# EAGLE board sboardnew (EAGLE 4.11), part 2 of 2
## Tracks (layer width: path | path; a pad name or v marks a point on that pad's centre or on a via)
-15V  (via drill 0.61)
  Top 0.635: v61.59,20.32 v56.52,15.24 | v203.2,28.58 v189.87,15.24
  Bottom 0.635: v56.52,15.24 55.88,15.24 55.88,13.97 U$1.DB2 | 117.47,20.32 v61.59,20.32 | 117.47,20.32 123.83,13.97 U$1.CB2 | 117.47,20.32 136.53,20.32 139.7,17.15 184.15,17.15 187.32,13.97 U$1.BB2 188.59,13.97 v189.87,15.24 | v203.2,28.58 232.41,28.58 242.57,18.42 252.73,18.42 257.18,13.97 U$1.AB2
A15U1  (via drill 0.61)
  Top 0.254: R11.2 R12.1 205.74,47.63 206.38,46.99 206.38,39.37 207.65,38.1 v207.65,15.88
  Bottom 0.254: v207.65,15.88 209.55,13.97 U$1.AU2
B17S1  (via drill 0.61)
  Top 0.254: E39.4 28.57,83.19 28.57,87 E39.1 | v216.53,179.07 217.81,177.8 217.81,121.29 E6.4 | v178.44,80.01 178.44,114.94 E12.4
  Bottom 0.254: 40.01,80.01 40.01,78.11 E39.9 | 40.01,80.01 33.02,80.01 31.75,81.28 E39.4 | E6.10 219.71,114.3 217.17,116.84 E6.4 209.55,116.84 207.01,114.3 E9.10 203.2,114.3 201.93,115.57 182.88,115.57 181.61,116.84 E12.4 | v216.53,179.07 215.9,179.07 214.63,180.34 E8.3 | v178.44,80.01 40.01,80.01
B17V1  (via drill 0.61)
  Top 0.254: E9.13 210.82,121.92 210.82,123.19 212.09,124.46 E6.1 | E3.3 230.5,118.75 230.5,117.48 E3.4 229.24,114.94 229.24,93.98 230.5,92.71 230.5,89.54 E2.1 | 226.06,82.55 R16.1 | 226.06,82.55 R15.2 | 226.06,82.55 222.25,86.36 E5.13 | E42.1 17.78,55.88 17.78,86.36 E43.1 | v147.96,86.36 147.96,53.98 E17.1
  Bottom 0.254: 223.52,120.65 224.79,119.38 E3.3 | 223.52,120.65 222.25,121.92 E6.13 | 223.52,120.65 208.28,120.65 207.01,121.92 E9.13 | E5.13 217.17,86.36 214.63,88.9 E5.1 212.09,88.9 209.55,86.36 v147.96,86.36 | R15.2 226.06,84.46 226.69,84.46 E2.1 234.95,88.9 237.49,86.36 E2.13 | E17.13 153.67,50.8 151.13,53.34 E17.1 146.05,53.34 143.51,50.8 E18.13 135.89,50.8 133.35,53.34 E18.1 130.81,53.34 129.54,54.61 34.29,54.61 31.75,52.07 17.78,52.07 | 17.78,52.07 19.05,50.8 E42.13 | 17.78,52.07 16.51,53.34 E42.1 | E43.13 21.59,86.36 19.05,88.9 E43.1
D01BINIT  (via drill 0.61)
  Top 0.254: v169.54,51.44 169.54,112.4 E15.4
  Bottom 0.254: E4.2 197.49,58.42 188.59,49.53 175.26,49.53 173.99,48.26 E14.15 v169.54,51.44
D01BTP2L  (via drill 0.61)
  Top 0.254: v177.16,123.83 177.8,124.46 177.8,144.78 E13.4
  Bottom 0.254: 177.16,123.19 228.6,123.19 229.87,121.92 E3.2 E3.13 | 177.16,123.19 167.64,123.19 166.37,121.92 E15.2 | 177.16,123.19 v177.16,123.83
D01DEL1H  (via drill 0.61)
  Top 0.254: v158.75,125.1 159.38,125.73 v159.38,128.27 159.38,144.15 E16.3
  Bottom 0.254: v158.75,125.1 149.22,115.57 121.92,115.57 118.11,111.76 E24.9 | v159.38,128.27 240.66,128.27 240.66,121.29 240.03,120.65 237.49,120.65 E3.5
D01DEL1L
  Top 0.254: E9.4 196.22,118.75 196.22,145.42 E10.4
  Bottom 0.254: E3.6 229.87,111.76 226.06,115.57 219.71,115.57 217.17,118.11 209.55,118.11 207.01,115.57 203.2,115.57 201.93,116.84 E9.4
D01DEL2  (via drill 0.61)
  Top 0.254: 116.2,57.79 104.78,57.79 100.33,53.34 E28.1 | 116.2,57.79 116.2,48.9 E22.1 | 116.2,57.79 116.84,58.42 116.84,72.39 118.11,72.39 118.75,73.03 118.75,89.54 114.94,93.35 114.94,114.94 E24.7 118.75,118.75 118.75,148.59 115.57,151.77 115.57,154.31 v120.02,158.75
  Bottom 0.254: v120.02,158.75 160.02,158.75 163.83,154.94 E16.1
D01DEL3  (via drill 0.61)
  Top 0.254: v192.41,127 195.58,130.18 195.58,147.32 E10.3
  Bottom 0.254: v192.41,127 E24.18 | E10.11 204.47,147.32 203.2,148.59 200.66,148.59 199.39,149.86 E10.3
D01DEL4
  Top 0.254: E3.9 236.85,113.67 236.85,139.07 238.12,140.34 238.12,181.61 231.78,187.96 196.22,187.96 196.22,182.25 E11.3 | E13.11 186.06,149.23 186.06,161.93 195.58,171.45 195.58,177.8 E11.3 | E9.3 201.29,122.56 201.29,177.17 E11.3
  Bottom 0.254: 121.92,123.19 101.6,123.19 100.33,124.46 E29.1 | 121.92,123.19 123.19,121.92 E24.16 | 121.92,123.19 121.92,128.27 142.24,128.27 142.88,127.64 155.57,127.64 165.1,137.16 165.1,138.43 181.61,138.43 186.69,143.51 189.23,143.51 189.87,144.15 189.87,146.69 188.59,146.69 E13.11
D01DEL5  (via drill 0.61)
  Top 0.254: v174.62,125.73 177.16,128.27 177.16,146.69 178.44,147.96 | 178.44,147.96 E13.3 | v194.31,171.45 178.44,155.58 178.44,147.96
  Bottom 0.254: v174.62,125.73 173.99,126.37 135.25,126.37 125.73,116.84 E24.14 | v194.31,171.45 203.2,171.45 204.47,172.72 E11.9
D01DONEH  (via drill 0.61)
  Top 0.254: v15.88,30.48 15.88,15.24 14.61,13.97 U$1.DS1 | v172.72,65.41 E15.8
  Bottom 0.254: v172.72,65.41 23.5,65.41 12.7,54.61 12.7,30.48 v15.88,30.48
D01DONEL  (via drill 0.61)
  Top 0.254: v167.64,111.76 166.37,113.03 163.19,113.03 163.19,132.08 167.64,136.53 v167.64,166.37
  Bottom 0.254: v167.64,166.37 170.18,168.91 | 170.18,168.91 201.93,168.91 203.2,170.18 E11.8 | v167.64,111.76 E15.9 | 170.18,168.91 169.54,168.91 151.13,187.33 139.06,187.33 E21.7
D01INHIBIT  (via drill 0.61)
  Top 0.254: v224.16,39.37 223.52,38.74 v223.52,15.24
  Bottom 0.254: v224.16,39.37 219.71,39.37 219.07,40.01 215.26,40.01 214.63,40.64 E4.9 | v223.52,15.24 223.52,13.97 U$1.AP2
D01INITL  (via drill 0.61)
  Top 0.254: 189.87,140.97 189.87,150.5 E13.13 189.23,152.4 v191.77,154.94 | 189.87,140.97 189.87,123.83 E12.13 | v197.49,57.15 177.16,77.47 177.16,121.29 E12.1 180.97,125.1 180.97,129.54 182.88,131.45 182.88,140.97 189.87,140.97 | v197.49,127 197.49,125.1 E9.1
  Bottom 0.254: E10.13 206.38,153.04 207.65,153.04 207.65,155.58 207.01,156.21 200.66,156.21 199.39,154.94 E10.1 v191.77,154.94 | E13.1 181.61,154.94 184.15,152.4 E13.13 | v197.49,57.15 218.44,57.15 219.71,55.88 E4.18 | v197.49,127 194.31,127 193.04,125.73 182.88,125.73 181.61,124.46 E12.1
D01LOADMDL  (via drill 0.61)
  Top 0.254: E39.5 32.38,80.65 32.38,84.46 E39.2 33.02,88.9 33.02,147.96 v33.66,148.59
  Bottom 0.254: E39.5 E39.10 | v33.66,148.59 48.26,148.59 58.42,158.75 90.81,158.75 90.81,181.61 95.89,186.69 99.69,186.69 102.23,189.23 151.76,189.23 168.28,172.72 E11.6
D01MEMDONEL
  Bottom 0.254: E21.5 143.51,186.69 150.5,186.69 151.13,186.06 151.13,181.61 126.36,181.61 125.09,180.34 H05/H24.28
D01MEMSTARTL  (via drill 0.61)
  Top 0.254: v223.52,114.3 223.52,116.84 E3.1
  Bottom 0.254: 185.42,113.03 186.69,114.3 E12.10 | 185.42,113.03 182.88,110.49 167.64,110.49 166.37,111.76 E15.6 | v223.52,114.3 222.25,113.03 185.42,113.03
D01POWEROK  (via drill 0.61)
  Top 0.254: v158.75,115.57 v158.75,31.12 | v142.88,18.42 v139.7,15.24
  Bottom 0.254: v158.75,115.57 160.02,115.57 163.83,119.38 E15.3 | v158.75,31.12 153.03,25.4 149.86,25.4 v142.88,18.42 | v139.7,15.24 138.43,13.97 U$1.BV2
D01READH  (via drill 0.61)
  Top 0.254: E11.4 197.49,177.17 197.49,175.9 E11.5 196.22,173.36 196.22,149.23 190.5,143.51 190.5,114.3 E12.9 | E3.11 238.12,116.21 238.12,114.94 E3.10 | v194.31,173.99 E16.13
  Bottom 0.254: E16.13 E16.2 | E12.9 189.23,111.76 190.5,110.49 233.68,110.49 237.49,114.3 E3.10 | v194.31,173.99 195.58,175.26 E11.5
D01READL  (via drill 0.61)
  Top 0.254: 190.5,109.22 196.22,109.22 196.22,114.94 196.85,115.57 201.93,115.57 201.93,151.13 204.47,153.67 207.65,153.67 207.65,173.36 E11.10 205.1,175.9 205.1,177.17 E11.11 | 190.5,109.22 E12.8 | v240.03,16.51 v238.76,15.24 | v205.74,27.31 198.75,34.29 198.75,95.89 190.5,104.14 190.5,109.22
  Bottom 0.254: v238.76,15.24 238.12,15.24 236.85,13.97 U$1.AK2 | v240.03,16.51 233.68,22.86 213.36,22.86 208.91,27.31 v205.74,27.31
D01RETURN  (via drill 0.61)
  Top 0.254: v222.25,15.24 222.88,15.88 222.88,48.9 E4.16
  Bottom 0.254: v222.25,15.24 220.98,13.97 U$1.AR2
D01SELECTH  (via drill 0.61)
  Top 0.254: v161.93,44.45 160.66,45.72 v160.66,117.48 | v182.25,120.65 182.25,116.21 E12.5
  Bottom 0.254: v161.93,44.45 170.18,44.45 171.45,43.18 E14.13 | v160.66,117.48 163.83,120.65 v182.25,120.65
D01SELECTL  (via drill 0.61)
  Top 0.254: v152.4,113.03 149.86,115.57 149.86,152.4 140.97,161.29 140.97,172.72 137.16,176.53 E21.2 137.16,181.61 139.7,184.15 E21.6
  Bottom 0.254: v152.4,113.03 177.8,113.03 179.07,111.76 E12.6
D01SELH  (via drill 0.61)
  Top 0.254: v184.15,130.18 184.15,125.73 E12.2
  Bottom 0.254: v184.15,130.18 194.94,140.97 210.82,140.97 212.09,142.24 E7.6
D01SELL
  Top 0.254: E7.5 210.82,147.32 210.82,185.42 212.09,186.69 219.07,186.69 219.07,179.71 E8.11
D01SOURCE  (via drill 0.61)
  Top 0.254: v222.88,54.61 227.33,50.17 v227.33,33.66 | v229.87,31.12 230.5,30.48 v230.5,15.24
  Bottom 0.254: v222.88,54.61 215.9,54.61 214.63,55.88 E4.3 | v229.87,31.12 v227.33,33.66 | v230.5,15.24 231.78,13.97 U$1.AL2
D01STROBE  (via drill 0.61)
  Top 0.254: v217.17,17.78 217.17,46.99 E4.5
  Bottom 0.254: v217.17,17.78 218.44,16.51 226.06,16.51 228.6,13.97 U$1.AM2
D01STROBEL
  Top 0.254: R18.1 R17.2 142.24,175.26 E21.3
  Bottom 0.254: H05/H24.24 125.09,175.26 126.36,173.99 147.96,173.99 149.22,175.26 R17.2
D01WRITE  (via drill 0.61)
  Top 0.254: v211.46,18.42 211.46,43.82 E4.7
  Bottom 0.254: v211.46,18.42 215.9,13.97 U$1.AS2
D01WRITEH
  Top 0.254: E16.5 164.47,145.42 164.47,146.69 E16.4 | E14.11 174.62,40.01 174.62,53.98 176.53,55.88 176.53,121.92 178.44,123.83 178.44,142.88 E13.5
  Bottom 0.254: E16.5 166.37,144.78 167.64,143.51 177.8,143.51 179.07,144.78 E13.5
D01WRITEL  (via drill 0.61)
  Top 0.254: E36.2 E36.7 E37.2 E37.7 | E40.2 E40.7 E41.2 E41.7 | v160.66,133.99 161.93,132.72 161.93,47.63 163.19,46.36 163.19,42.55 E14.9 | v85.72,142.88 82.55,146.05 82.55,160.02 81.28,161.29 E33.2 E33.7 E34.2 E34.7
  Bottom 0.254: E41.2 27.94,177.8 33.66,177.8 37.47,173.99 49.53,173.99 E36.7 55.88,172.72 66.67,172.72 67.94,171.45 77.47,171.45 78.11,172.09 79.38,172.09 E33.7 | v160.66,133.99 151.76,142.88 v85.72,142.88
D02MEM0  (via drill 0.61)
  Top 0.254: v110.49,150.5 110.49,149.86 111.76,148.59 E25.3
  Bottom 0.254: v110.49,150.5 109.22,151.77 101.6,151.77 99.69,153.67 98.42,153.67 97.16,154.94 H04/H23.8
D02MEM1
  Bottom 0.254: E25.5 110.49,158.75 98.42,158.75 97.16,160.02 H04/H23.12
D02MEM2
  Top 0.254: E32.3 83.82,148.59 87.63,152.4 87.63,155.58 96.52,164.47 H04/H23.16
D02MEM3
  Top 0.254: E32.5 86.36,156.21 95.25,165.1 95.25,168.28 96.52,169.55 H04/H23.20
D02MEM4
  Bottom 0.254: E26.3 102.87,171.45 102.23,171.45 99.69,173.99 98.42,173.99 97.16,175.26 H04/H23.24
D02MEM5
  Top 0.254: E26.5 114.3,171.45 110.49,175.26 110.49,186.69 107.95,189.23 97.79,189.23 97.79,182.25 96.52,180.98 H04/H23.28
D02MEM6
  Bottom 0.254: E27.3 107.95,181.61 98.42,181.61 97.16,182.88 H04/H23.30
D02MEM7
  Bottom 0.254: E27.5 112.39,183.52 100.33,183.52 99.69,184.15 98.42,184.15 97.16,185.42 H04/H23.32
D02MEM8  (via drill 0.61)
  Top 0.254: v139.7,151.13 E19.3
  Bottom 0.254: v139.7,151.13 126.36,151.13 125.09,152.4 H05/H24.6
D02MEM9
  Bottom 0.254: E19.5 140.34,153.04 128.27,153.04 127.64,153.67 126.36,153.67 125.09,154.94 H05/H24.8
D02MEM10
  Bottom 0.254: E20.3 137.79,160.66 128.27,160.66 127.64,161.29 126.36,161.29 125.09,160.02 H05/H24.12
D02MEM11
  Bottom 0.254: E20.5 145.41,170.18 146.05,169.55 146.05,166.37 126.36,166.37 125.09,165.1 H05/H24.16
D03BEMA0L  (via drill 0.61)
  Top 0.254: v210.19,111.76 207.65,109.22 207.65,40.64 210.19,38.1 v210.19,33.02 | v247.65,19.69 249.56,17.78 v249.56,15.24
  Bottom 0.254: v210.19,33.02 213.36,29.85 237.49,29.85 v247.65,19.69 | v249.56,15.24 250.82,13.97 U$1.AD2 | v210.19,111.76 E6.6
D03BEMA1L  (via drill 0.61)
  Top 0.254: v246.38,94.62 246.38,16.51 v247.65,15.24
  Bottom 0.254: v246.38,94.62 233.04,107.95 223.52,107.95 222.25,109.22 E6.8 | v247.65,15.24 247.65,13.97 U$1.AE2
D03BEMA2L  (via drill 0.61)
  Top 0.254: v208.91,26.04 208.91,38.1 207.01,40.01 207.01,107.95 E9.8
  Bottom 0.254: v208.91,26.04 215.9,19.05 236.22,19.05 241.3,13.97 U$1.AH2
D03BMA0
  Bottom 0.254: E1.11 237.49,38.1 236.22,36.83 174.62,36.83 170.18,32.39 153.67,32.39 149.22,27.94 15.88,27.94 10.16,22.23 5.08,22.23 1.91,25.4 1.91,158.75 13.34,158.75 13.97,159.39 13.97,164.47 12.7,164.47 H01/H20.16
D03BMA1  (via drill 0.61)
  Top 0.254: v233.68,104.78 234.31,104.14 234.31,75.57 233.68,74.93 233.68,53.34 236.22,50.8 236.22,45.72 E1.13 | v15.24,137.16 13.97,138.43 13.97,168.28 12.7,169.55 H01/H20.20
  Bottom 0.254: v233.68,104.78 226.06,97.16 55.24,97.16 v15.24,137.16
D03BMA2
  Bottom 0.254: E1.15 243.21,48.26 248.92,53.98 248.92,192.41 15.24,192.41 11.43,188.6 11.43,175.9 12.7,175.9 H01/H20.24
D03BMA3  (via drill 0.61)
  Top 0.254: v154.94,64.14 153.67,65.41 153.67,177.17 v140.34,190.5
  Bottom 0.254: v154.94,64.14 240.66,64.14 240.66,55.25 E1.17 | v140.34,190.5 139.7,191.14 25.4,191.14 15.88,181.61 14.61,181.61 13.34,180.34 H01/H20.28
D03BMA4  (via drill 0.61)
  Top 0.254: v144.15,62.87 139.7,67.31 v139.7,93.35 | v13.97,137.16 11.43,139.7 11.43,180.98 12.7,182.25 H01/H20.30
  Bottom 0.254: v144.15,62.87 159.38,62.87 163.83,58.42 E14.2 | v139.7,93.35 136.53,96.52 54.61,96.52 v13.97,137.16
D03BMA5  (via drill 0.61)
  Top 0.254: v157.48,55.88 156.21,57.15 v156.21,186.06
  Bottom 0.254: v157.48,55.88 161.29,55.88 163.83,53.34 E14.4 | v156.21,186.06 150.5,191.77 20.95,191.77 15.88,186.69 14.61,186.69 13.34,185.42 H01/H20.32
D03BMA6  (via drill 0.61)
  Top 0.254: v47.62,60.96 45.72,62.87 v45.72,149.86
  Bottom 0.254: v47.62,60.96 53.34,55.25 150.5,55.25 153.67,52.07 167,52.07 167,50.17 E14.6 | v45.72,149.86 44.45,151.13 42.55,151.13 41.27,152.4 H02/H21.6
D03BMA7  (via drill 0.61)
  Top 0.254: v53.34,64.14 50.16,67.31 v50.16,151.77
  Bottom 0.254: v53.34,64.14 70.48,64.14 73.03,61.6 135.25,61.6 139.7,57.15 167.64,57.15 167.64,48.26 166.37,46.99 160.66,46.99 160.66,44.45 161.93,43.18 E14.8 | v50.16,151.77 48.26,153.67 42.55,153.67 41.27,154.94 H02/H21.8
D03BMA8  (via drill 0.61)
  Top 0.254: v34.29,60.96 34.92,61.6 34.92,153.67 40.64,159.39 H02/H21.12
  Bottom 0.254: v34.29,60.96 31.75,58.42 E38.2
D03BMA9  (via drill 0.61)
  Top 0.254: v20.95,60.33 19.68,61.6 19.68,146.69 26.67,153.67 26.67,158.75 29.21,161.29 29.21,163.83 30.48,165.1 H02/H21.16
  Bottom 0.254: v20.95,60.33 22.23,60.33 29.21,53.34 E38.4
D03BMA10  (via drill 0.61)
  Top 0.254: v34.29,50.8 35.56,52.07 35.56,140.34 41.91,146.69 41.91,168.28 40.64,169.55 H02/H21.20
  Bottom 0.254: v34.29,50.8 31.75,48.26 E38.6
D03BMA11  (via drill 0.61)
  Top 0.254: v43.18,41.91 44.45,43.18 44.45,188.6 43.81,189.23 41.91,189.23 41.91,177.17 40.64,175.9 H02/H21.24
  Bottom 0.254: v43.18,41.91 33.02,41.91 31.75,43.18 E38.8
D03BTP2  (via drill 0.61)
  Top 0.254: 168.91,120.65 169.54,120.02 v169.54,116.21 | 168.91,120.65 E15.1 | 168.91,120.65 v168.91,170.82
  Bottom 0.254: v169.54,116.21 170.18,115.57 176.53,115.57 179.07,118.11 185.42,118.11 186.69,116.84 E12.11 | v168.91,170.82 151.76,187.96 134.62,187.96 133.35,186.69 126.36,186.69 125.09,185.42 H05/H24.32
D03EA0  (via drill 0.61)
  Top 0.254: v74.3,66.68 71.12,69.85 71.12,100.33 71.75,100.97 71.75,144.78 69.85,146.69 69.85,150.5 68.58,151.77 H03/H22.6
  Bottom 0.254: v74.3,66.68 241.3,66.68 241.3,53.34 240.03,52.07 237.49,52.07 E1.2
D03EA1  (via drill 0.61)
  Top 0.254: v210.19,52.07 208.91,53.34 v208.91,98.43 | v70.48,100.97 68.58,102.87 68.58,145.42 67.31,146.69 67.31,153.04 68.58,154.31 H03/H22.8
  Bottom 0.254: v210.19,52.07 228.6,52.07 229.87,53.34 E1.4 | v208.91,98.43 206.38,100.97 v70.48,100.97
D03EA2  (via drill 0.61)
  Top 0.254: v204.47,49.53 199.39,54.61 v199.39,103.51 | v67.31,133.35 66.67,133.99 66.67,157.48 68.58,159.39 H03/H22.12
  Bottom 0.254: v204.47,49.53 228.6,49.53 229.87,48.26 E1.6 | v199.39,103.51 198.75,104.14 96.52,104.14 v67.31,133.35
D03EMA0H  (via drill 0.61)
  Top 0.254: v216.53,137.16 216.53,121.92 E6.2 | E8.9 222.88,170.82 222.88,141.61 E7.8
  Bottom 0.254: E8.9 222.25,172.72 224.79,175.26 226.69,175.26 231.14,179.71 JP1.1 | v216.53,137.16 219.07,139.7 E7.8
D03EMA0L  (via drill 0.61)
  Top 0.254: E8.4 211.46,175.9 211.46,156.85 E7.1 216.53,151.77 v216.53,142.24 | v235.59,57.15 v235.59,140.34
  Bottom 0.254: JP1.3 233.04,180.34 231.78,181.61 224.79,181.61 222.25,179.07 217.81,179.07 216.53,177.8 E8.4 | v235.59,57.15 236.22,57.15 237.49,55.88 E1.18 | v235.59,140.34 234.95,140.97 223.52,140.97 222.25,142.24 E7.9 v216.53,142.24
D03EMA1H
  Top 0.254: 218.44,142.24 218.44,121.92 E6.12 | 218.44,142.24 E7.10 | 218.44,142.24 218.44,175.26 E8.10
  Bottom 0.254: JP2.3 233.04,167.64 231.78,168.91 230.5,168.91 227.97,171.45 219.71,171.45 219.07,172.09 219.07,175.26 E8.10
D03EMA1L  (via drill 0.61)
  Top 0.254: v234.95,53.34 234.31,53.98 234.31,74.3 234.95,74.93 234.95,136.53 229.87,141.61 v229.87,147.32 229.87,165.74 231.14,167.01 JP2.1
  Bottom 0.254: v234.95,53.34 237.49,50.8 E1.16 | v229.87,147.32 E7.11 | E8.5 219.71,168.91 229.24,168.91 230.5,167.64 JP2.1
D03EMA2H  (via drill 0.61)
  Top 0.254: v203.2,151.13 203.2,121.92 E9.12
  Bottom 0.254: v203.2,151.13 218.44,151.13 219.71,149.86 E7.12 225.43,149.86 230.5,154.94 JP3.1
D03EMA2L
  Top 0.254: E1.14 236.85,47.63 236.85,69.85 236.22,70.49 236.22,139.7 237.49,140.97 237.49,150.5 233.68,154.31 JP3.3
  Bottom 0.254: E7.13 222.25,152.4 226.06,156.21 231.78,156.21 233.04,154.94 JP3.3
D03MA0L  (via drill 0.61)
  Top 0.254: v247.65,39.37 251.46,35.56 251.46,13.97 U$1.AD1
  Bottom 0.254: v247.65,39.37 233.68,39.37 232.41,40.64 E1.9
D03MA1L  (via drill 0.61)
  Top 0.254: v244.47,41.91 245.75,40.64 245.75,15.88 247.65,13.97 U$1.AE1
  Bottom 0.254: v244.47,41.91 236.22,41.91 232.41,45.72 E1.7
D03MA2L  (via drill 0.61)
  Top 0.254: v243.21,49.53 243.21,13.97 U$1.AH1
  Bottom 0.254: v243.21,49.53 233.68,49.53 232.41,50.8 E1.5
D03MA3L
  Top 0.254: E1.3 233.04,53.98 233.04,50.17 235.59,47.63 235.59,16.51 238.12,13.97 U$1.AJ1
D03MA4L  (via drill 0.61)
  Top 0.254: v177.8,50.8 180.97,47.63 180.97,13.97 U$1.BD1
  Bottom 0.254: v177.8,50.8 E14.18
D03MA5L  (via drill 0.61)
  Top 0.254: v175.9,50.8 177.8,48.9 177.8,13.97 U$1.BE1
  Bottom 0.254: v175.9,50.8 E14.16
D03MA6L  (via drill 0.61)
  Top 0.254: v175.9,43.18 175.26,42.55 v175.26,20.32 | v173.35,18.42 173.35,13.97 U$1.BH1
  Bottom 0.254: v175.9,43.18 175.26,43.18 E14.14 | v173.35,18.42 v175.26,20.32
D03MA7L  (via drill 0.61)
  Top 0.254: v163.19,39.37 163.19,19.05 168.28,13.97 U$1.BJ1
  Bottom 0.254: v163.19,39.37 170.18,39.37 171.45,40.64 E14.12
D03MA8L
  Top 0.254: E38.18 41.91,52.07 41.91,19.69 47.62,13.97 U$1.DD1
D03MA9L
  Top 0.254: E38.16 41.27,47.63 41.27,17.15 44.45,13.97 U$1.DE1
D03MA10L  (via drill 0.61)
  Top 0.254: v38.1,21.59 38.1,26.04 35.56,28.58 35.56,43.18 E38.14 | v37.47,18.42 37.47,14.61 38.1,13.97 U$1.DH1
  Bottom 0.254: v38.1,21.59 38.1,18.42 v37.47,18.42
D03MA11L  (via drill 0.61)
  Top 0.254: v40.01,19.05 40.01,38.74 E38.12 | v36.2,15.24 36.2,13.97 U$1.DJ1
  Bottom 0.254: v36.2,15.24 v40.01,19.05
D03MCBMB0L
  Bottom 0.254: E37.1 49.53,179.07 42.55,179.07 41.27,180.34 H02/H21.28
D03MCBMB1L
  Bottom 0.254: E37.6 57.78,187.33 59.69,187.33 62.23,184.79 62.23,181.61 42.55,181.61 41.27,182.88 H02/H21.30
D03MCBMB2L
  Bottom 0.254: E41.6 30.48,185.42 H02/H21.32
D03MCBMB3L
  Bottom 0.254: E40.1 21.59,153.67 14.61,153.67 13.34,152.4 H01/H20.6
D03MCBMB4L
  Bottom 0.254: E40.6 26.04,164.47 22.23,164.47 16.51,158.75 16.51,156.21 14.61,156.21 13.34,154.94 H01/H20.8
D03MCBMB5L
  Bottom 0.254: E41.1 21.59,173.99 12.06,173.99 11.43,173.36 11.43,160.66 12.7,160.66 H01/H20.12
D03MCBMB6L
  Bottom 0.254: E36.1 53.34,165.1 H03/H22.16
D03MCBMB7L
  Bottom 0.254: E36.6 57.78,172.09 66.04,172.09 67.94,170.18 H03/H22.20
D03MCBMB8L  (via drill 0.61)
  Top 0.254: v74.93,176.53 74.93,167.64 78.74,163.83 E33.1
  Bottom 0.254: v74.93,176.53 70.48,176.53 69.22,175.26 H03/H22.24
D03MCBMB9L
  Bottom 0.254: E33.6 80.01,173.99 67.94,173.99 67.31,174.63 67.31,180.34 H03/H22.28
D03MCBMB10L
  Bottom 0.254: E34.1 74.93,181.61 70.48,181.61 69.22,182.88 H03/H22.30
D03MCBMB11L
  Bottom 0.254: E34.6 81.92,183.52 72.39,183.52 71.75,184.15 70.48,184.15 69.22,185.42 H03/H22.32
D03MEMSTART  (via drill 0.61)
  Top 0.254: v128.27,114.3 v128.27,168.91
  Bottom 0.254: E6.11 219.71,116.84 217.17,119.38 E6.3 209.55,119.38 207.01,116.84 E9.11 204.47,116.84 203.2,118.11 186.69,118.11 185.42,119.38 E12.3 179.07,119.38 177.8,118.11 170.18,118.11 166.37,114.3 E15.5 v128.27,114.3 | v128.27,168.91 126.36,168.91 125.09,170.18 H05/H24.20
D04MD0L  (via drill 0.61)
  Top 0.254: U$1.AK1 234.95,13.97 234.95,46.99 229.87,46.99 229.24,47.63 v229.24,85.09 229.24,92.71 v223.52,98.43 | v64.77,106.05 64.77,167.64 55.88,176.53 E37.3
  Bottom 0.254: v229.24,85.09 236.22,85.09 237.49,83.82 E2.12 | v64.77,106.05 68.58,102.24 95.89,102.24 96.52,101.6 212.09,101.6 215.26,98.43 v223.52,98.43
D04MD1L  (via drill 0.61)
  Top 0.254: v240.66,85.09 240.66,19.05 v237.49,15.88 | v233.68,15.88 233.68,13.97 U$1.AL1 | v66.04,95.25 66.04,176.53 58.42,184.15 E37.5
  Bottom 0.254: v237.49,15.88 v233.68,15.88 | E2.2 232.41,86.36 233.04,85.73 236.85,85.73 237.49,85.09 v240.66,85.09 240.66,89.54 238.76,91.44 69.85,91.44 v66.04,95.25
D04MD2L  (via drill 0.61)
  Top 0.254: E5.12 228.6,76.2 228.6,45.72 229.87,44.45 233.68,44.45 233.68,17.15 230.5,13.97 U$1.AM1 | v154.94,83.82 154.94,192.41 40.01,192.41 E41.5
  Bottom 0.254: v154.94,83.82 156.21,82.55 218.44,82.55 219.71,83.82 E5.12
D04MD3L  (via drill 0.61)
  Top 0.254: 215.26,84.46 217.81,81.92 217.81,18.42 222.25,13.97 U$1.AP1 | 215.26,84.46 E5.2 | v30.48,137.16 30.48,151.13 27.94,153.67 E40.3 | v212.72,102.24 215.26,99.7 215.26,84.46
  Bottom 0.254: v30.48,137.16 60.33,107.32 92.08,107.32 97.16,102.24 v212.72,102.24
D04MD4L  (via drill 0.61)
  Top 0.254: 156.84,46.36 157.48,45.72 157.48,21.59 165.1,13.97 U$1.BK1 | 156.84,46.36 E17.12 | v31.75,118.11 31.75,160.02 30.48,161.29 E40.5 | v150.5,90.17 153.03,87.63 153.03,57.79 156.84,53.98 156.84,46.36
  Bottom 0.254: v31.75,118.11 59.69,90.17 v150.5,90.17
D04MD5L  (via drill 0.61)
  Top 0.254: 149.22,48.9 150.5,47.63 v150.5,24.13 | v157.48,18.42 161.93,13.97 U$1.BL1 | 149.22,48.9 E17.2 | 149.22,48.9 149.22,121.29 143.51,127 143.51,156.21 138.43,161.29 138.43,171.45 135.89,173.99 135.89,191.14 41.91,191.14 39.37,188.6 39.37,180.34 33.02,180.34 E41.3
  Bottom 0.254: v150.5,24.13 156.21,18.42 v157.48,18.42
D04MD6L  (via drill 0.61)
  Top 0.254: v151.13,49.53 151.76,48.9 151.76,20.96 158.75,13.97 U$1.BM1 | v62.23,60.96 62.23,154.94 55.88,161.29 E36.3 | v135.25,60.33 141.6,53.98 141.6,50.17 E18.12
  Bottom 0.254: v151.13,49.53 142.24,49.53 140.97,48.26 E18.12 | v62.23,60.96 62.87,60.33 v135.25,60.33
D04MD7L  (via drill 0.61)
  Top 0.254: 133.99,48.9 136.53,46.36 v136.53,26.67 | v147.32,24.13 152.4,19.05 152.4,13.97 U$1.BP1 | 133.99,48.9 E18.2 | v63.5,144.15 63.5,163.83 58.42,168.91 E36.5 | v129.54,139.7 130.81,138.43 130.81,85.73 132.08,84.46 132.08,55.88 133.99,53.98 133.99,48.9
  Bottom 0.254: v136.53,26.67 139.06,24.13 v147.32,24.13 | v63.5,144.15 67.94,139.7 v129.54,139.7
D04MD8L  (via drill 0.61)
  Top 0.254: 24.77,81.92 28.57,78.11 28.57,17.15 31.75,13.97 U$1.DK1 | 24.77,81.92 E43.12 | v29.21,146.69 24.77,142.24 24.77,81.92
  Bottom 0.254: v29.21,146.69 38.73,156.21 54.61,156.21 59.69,161.29 71.75,161.29 74.93,164.47 81.92,164.47 E33.3
D04MD9L  (via drill 0.61)
  Top 0.254: v24.77,80.01 27.94,76.84 27.94,14.61 28.57,13.97 U$1.DL1 | v20.32,166.37 16.51,162.56 16.51,92.71 13.34,89.54 13.34,88.27 E43.2
  Bottom 0.254: v24.77,80.01 24.77,81.92 24.13,82.55 20.32,82.55 16.51,86.36 E43.2 | v20.32,166.37 90.17,166.37 90.17,169.55 89.53,170.18 E33.5
D04MD10L  (via drill 0.61)
  Top 0.254: v26.04,45.72 26.04,13.97 U$1.DM1 | v54.61,48.26 54.61,189.23 85.09,189.23 87.63,186.69 87.63,182.88 83.82,179.07 E34.3
  Bottom 0.254: 24.13,46.99 25.4,45.72 v26.04,45.72 | 24.13,46.99 E42.12 | v54.61,48.26 53.34,46.99 24.13,46.99
D04MD11L  (via drill 0.61)
  Top 0.254: E42.2 19.05,46.99 19.05,13.97 U$1.DP1 | v71.12,62.23 75.56,66.68 73.66,68.58 73.66,187.33 84.45,187.33 E34.5
  Bottom 0.254: v71.12,62.23 21.59,62.23 13.34,53.98 13.34,51.44 14.61,51.44 E42.2
GND  (via drill 0.61)
  Top 0.635: E14.10 166.37,36.83 C19.2 | C19.2 166.37,34.93 169.54,31.75 169.54,26.67 C50.- 170.81,24.13 170.81,22.86 174.62,19.05 174.62,13.97 U$1.BF1 | E14.1 167,59.06 167,35.56 C19.2 | v182.88,15.24 184.15,13.97 U$1.BC1 | v154.31,15.24 155.57,13.97 U$1.BN2 | C22.2 148.59,36.83 E17.7 146.05,38.1 v146.05,15.24 144.78,13.97 U$1.BT2 | E22.4 118.11,39.37 C27.2 118.11,15.24 | E18.7 133.35,36.83 C23.2 | v20.95,15.24 22.23,13.97 U$1.DN2 | E43.7 16.51,72.39 C48.2 | E39.7 31.75,72.39 C44.2 31.75,62.23 E38.1 32.38,59.06 32.38,35.56 C43.2 | C47.2 16.51,36.83 E42.7 14.61,37.47 14.61,17.15 11.43,13.97 U$1.DT2 | E38.10 31.75,36.83 C43.2 | C43.2 31.75,29.85 34.92,26.67 C52.- 36.2,24.13 36.2,21.59 38.73,19.05 38.73,16.51 41.27,13.97 U$1.DF1 | R19.1 D1.A | E31.7 82.55,72.39 C36.2 82.55,68.58 78.74,64.77 D2.A R21.1 75.56,63.5 61.59,49.53 61.59,34.29 | D3.A R25.1 | R27.1 D4.A 114.3,64.77 115.57,66.04 115.57,73.66 E23.7 | U$1.CT2 81.28,13.97 82.55,15.24 92.08,15.24 92.08,13.97 U$1.CN2 93.98,13.97 103.5,23.5 103.5,24.13 C51.- | E30.7 82.55,36.83 C35.2 | E35.4 64.77,39.37 C40.2 64.77,37.47 61.59,34.29 | E28.7 100.33,36.83 C33.2 100.33,34.93 103.5,31.75 103.5,26.67 C51.- | C51.- 104.78,24.13 111.12,17.78 111.12,13.97 U$1.CF1 113.03,13.97 113.03,15.24 v114.3,15.24 118.11,15.24 | 61.59,34.29 55.88,28.58 55.88,17.15 52.7,13.97 U$1.DC1 | 118.11,15.24 119.38,15.24 120.65,13.97 U$1.CC1 | H01/H20.1 H01/H20.3 H01/H20.5 H01/H20.7 H01/H20.9 H01/H20.11 H01/H20.13 H01/H20.15 H01/H20.17 H01/H20.19 H01/H20.21 H01/H20.23 H01/H20.25 H01/H20.27 H01/H20.29 H01/H20.31 H01/H20.33 | H02/H21.1 H02/H21.3 H02/H21.5 H02/H21.7 H02/H21.9 H02/H21.11 H02/H21.13 H02/H21.15 H02/H21.17 H02/H21.19 H02/H21.21 H02/H21.23 H02/H21.25 H02/H21.27 H02/H21.29 H02/H21.31 H02/H21.33
  Top 0.635: H03/H22.1 H03/H22.3 H03/H22.5 H03/H22.7 H03/H22.9 H03/H22.11 H03/H22.13 H03/H22.15 H03/H22.17 H03/H22.19 H03/H22.21 H03/H22.23 H03/H22.25 H03/H22.27 H03/H22.29 H03/H22.31 H03/H22.33 | H04/H23.1 H04/H23.3 H04/H23.5 H04/H23.7 H04/H23.9 H04/H23.11 H04/H23.13 H04/H23.15 H04/H23.17 H04/H23.19 H04/H23.21 H04/H23.23 H04/H23.25 H04/H23.27 H04/H23.29 H04/H23.31 H04/H23.33 | H05/H24.33 H05/H24.31 H05/H24.29 H05/H24.27 H05/H24.25 H05/H24.23 H05/H24.21 H05/H24.19 H05/H24.17 H05/H24.15 H05/H24.13 H05/H24.11 H05/H24.9 H05/H24.7 H05/H24.5 H05/H24.3 H05/H24.1 127,146.69 126.36,146.05 126.36,131.45 E24.19 122.56,127.64 122.56,122.56 | E25.4 114.3,146.05 116.2,144.15 116.2,132.72 E24.1 | E29.7 99.69,108.59 99.69,107.95 100.33,107.32 C34.2 100.33,104.14 96.52,100.33 D5.A | 122.56,118.75 123.19,119.38 E24.15 | 122.56,118.75 118.75,114.94 | 118.75,114.94 118.11,114.3 E24.8 | 122.56,122.56 122.56,118.75 | 122.56,122.56 E24.17 | 118.75,114.94 118.75,111.13 E24.10 117.47,108.59 117.47,107.95 118.11,107.32 C29.2 118.11,106.05 120.02,104.14 120.02,72.39 118.75,71.12 C28.2 | v244.47,15.24 244.47,13.97 U$1.AF1 | v252.73,15.24 254,13.97 U$1.AC1 | E1.8 229.24,41.28 229.24,40.01 E1.10 232.41,36.83 C6.2 231.78,35.56 226.69,30.48 226.69,26.67 C49.- 225.43,24.13 v225.43,15.24 225.43,13.97 U$1.AN2 | E1.1 231.78,61.6 231.78,69.85 232.41,70.49 C7.2 232.41,71.76 231.78,72.39 231.78,73.03 E2.7 233.04,75.57 233.04,103.51 232.41,104.14 C8.2 232.41,107.95 E3.7 | 215.26,38.1 215.26,35.56 C9.2 214.63,13.97 U$1.AT2 212.72,13.97 v212.72,15.24 | 215.26,41.28 215.26,38.1
  Top 0.635: 215.26,41.28 E4.8 | 215.26,41.28 215.26,46.36 E4.6 211.46,50.17 211.46,59.06 E4.1 214,61.6 214,69.85 214.63,70.49 C10.2 214.63,72.39 E5.7 | 215.26,38.1 E4.10 | E6.7 214.63,107.95 C11.2 | C14.2 199.39,107.32 198.75,107.95 198.75,108.59 E9.7 | E15.7 166.37,107.95 C20.2 | E12.7 180.97,108.59 180.97,107.95 181.61,107.32 C17.2 182.25,106.68 182.25,114.94 186.69,119.38 E12.12 | E8.1 212.72,184.79 212.72,183.52 E8.2 215.26,180.98 215.26,167.64 C13.2 214.63,168.91 E8.7 | C21.2 166.37,137.8 165.74,138.43 165.74,139.07 E16.7 | C18.2 181.61,137.8 180.97,138.43 180.97,139.07 E13.7 182.25,141.61 182.25,150.5 E13.2 | E11.7 199.39,168.91 C16.2 199.39,167.01 200.03,166.37 200.03,150.5 | C12.2 214.63,138.43 E7.7 207.65,145.42 207.65,147.96 E10.12 | 200.03,150.5 200.03,141.61 E10.7 198.75,139.07 198.75,138.43 199.39,137.8 C15.2 200.03,137.16 200.03,123.83 E9.2 | E10.2 200.03,150.5
  Bottom 0.635: E14.19 168.91,58.42 166.37,60.96 E14.1 E14.17 | U$1.BC2 184.15,13.97 v182.88,15.24 177.8,15.24 176.53,13.97 U$1.BF2 174.62,13.97 173.35,15.24 v154.31,15.24 | v154.31,15.24 v146.05,15.24 144.78,13.97 U$1.BT2 | v154.31,15.24 155.57,13.97 U$1.BN2 | C27.2 118.75,38.1 121.28,35.56 C23.2 | E17.7 146.05,38.1 144.78,39.37 134.62,39.37 133.35,38.1 E18.7 | C19.2 165.74,35.56 164.47,34.29 150.5,34.29 149.22,35.56 C22.2 | U$1.DT2 11.43,13.97 12.7,15.24 v20.95,15.24 22.23,13.97 U$1.DN2 24.13,13.97 34.29,24.13 34.92,24.13 C52.- 36.2,24.13 41.27,24.13 41.27,15.24 | C48.2 17.14,71.12 18.41,69.85 29.84,69.85 31.11,71.12 C44.2 | C47.2 17.14,35.56 18.41,36.83 27.94,36.83 29.21,38.1 E38.10 | 41.27,15.24 41.27,13.97 U$1.DF2 | 41.27,15.24 49.53,15.24 50.8,13.97 U$1.DC2 | U$1.CC2 120.65,13.97 119.38,15.24 v114.3,15.24 113.03,13.97 U$1.CF2 111.12,13.97 109.86,15.24 90.81,15.24 | 90.81,15.24 82.55,15.24 81.28,13.97 U$1.CT2 | 90.81,15.24 92.08,13.97 U$1.CN2 | D1.A 90.81,62.87 79.38,62.87 D2.A | E23.7 117.47,73.03 117.47,71.76 118.11,71.76 C28.2 | D3.A 126.36,62.87 114.94,62.87 D4.A | R27.1 R19.1 | E30.7 80.01,38.1 78.74,36.83 66.67,36.83 65.41,38.1 C40.2 | C35.2 83.19,35.56 84.45,36.83 96.52,36.83 97.79,38.1 E28.7 | C43.2 32.38,35.56 33.66,36.83 58.42,36.83 62.23,40.64 E35.4 | C46.2 31.75,176.53 E41.4 27.94,172.72 H01/H20.21 | C45.2 31.75,156.21 E40.4 27.94,152.4 | 27.94,152.4 H01/H20.5 | C42.2 59.69,179.07 E37.4 55.88,175.26 H02/H21.23 | C41.2 59.69,163.83 E36.4 55.88,160.02 H02/H21.11 | 27.94,152.4 27.94,145.42 40.64,145.42 42.55,147.32 H02/H21.1 43.81,147.32 45.72,145.42 68.58,145.42 70.48,147.32 H03/H22.1
  Bottom 0.635: C39.2 87.63,179.07 E34.4 83.82,175.26 H03/H22.23 | C38.2 87.63,163.83 E33.4 83.82,160.02 H03/H22.11 | H03/H22.3 83.82,149.86 E32.4 87.63,148.59 C37.2 89.53,148.59 92.71,145.42 96.52,145.42 98.42,147.32 H04/H23.1 | C32.2 115.57,179.07 E27.4 111.76,175.26 H04/H23.23 | C31.2 115.57,163.83 E26.4 111.76,160.02 H04/H23.11 | R18.2 149.22,162.56 147.96,163.83 C25.2 143.51,163.83 E20.4 139.7,165.1 H05/H24.15 | C26.2 143.51,179.07 E21.4 139.7,175.26 H05/H24.23 | H05/H24.3 139.7,149.86 E19.4 143.51,148.59 C24.2 145.41,148.59 147.32,146.69 155.57,146.69 162.56,139.7 E16.7 | E25.4 115.57,148.59 C30.2 116.84,149.23 100.33,149.23 99.69,149.86 H04/H23.3 | E24.19 123.19,129.54 120.65,132.08 E24.1 | D5.A R29.1 | C34.2 100.97,106.68 102.23,105.41 116.2,105.41 117.47,106.68 C29.2 | U$1.AC2 254,13.97 v252.73,15.24 251.46,16.51 246.38,16.51 246.38,13.97 U$1.AF2 244.47,13.97 v244.47,15.24 234.95,24.77 227.33,24.77 C49.- | v225.43,15.24 225.43,13.97 U$1.AN2 | R16.2 226.69,71.12 229.24,73.66 E2.7 | E1.19 234.95,58.42 232.41,60.96 E1.1 229.87,60.96 227.33,58.42 E4.19 217.17,58.42 214.63,60.96 E4.1 | E4.10 R12.2 | v212.72,15.24 212.72,13.97 U$1.AT2 | E1.8 229.87,43.18 228.6,44.45 215.9,44.45 214.63,43.18 E4.8 | E12.12 189.23,119.38 191.77,121.92 E9.2 | 177.8,107.95 168.28,107.95 167,106.68 C20.2 | 177.8,107.95 179.07,109.22 E12.7 | 177.8,107.95 195.58,107.95 196.85,109.22 E9.7 | 212.72,105.41 214,106.68 C11.2 | 212.72,105.41 201.29,105.41 200.03,106.68 C14.2 | 212.72,105.41 230.5,105.41 231.78,106.68 C8.2 | JP2.5 235.59,167.64 233.68,165.74 228.6,165.74 227.97,166.37 216.53,166.37 215.26,167.64 C13.2
  Bottom 0.635: C21.2 167,137.16 168.28,135.89 179.71,135.89 180.97,137.16 C18.2 | E10.12 201.93,149.86 199.39,152.4 E10.2 191.77,152.4 189.23,149.86 E13.12 184.15,149.86 181.61,152.4 E13.2 | E8.7 212.09,170.18 210.82,168.91 203.2,168.91 201.93,167.64 C16.2
  pour Bottom: 0,213.36 264.16,213.36 264.16,20.32 0,20.32
  pour Top: 0,213.36 264.16,213.36 264.16,20.32 0,20.32
N$3
  Top 0.254: E23.10 123.83,78.11 123.83,76.84 E23.9 D3.C R25.2 C3.2
N$5
  Top 0.254: E29.5 98.42,114.94 98.42,116.21 E29.4 | D5.C R29.2 C5.2
  Bottom 0.254: E29.5 97.79,114.3 95.25,111.76 C5.2
N$7  (via drill 0.61)
  Top 0.254: v225.43,144.78 225.43,178.44 E8.13 | JP4.4 JP4.6
  Bottom 0.254: v225.43,144.78 JP4.2 JP4.4
N$8
  Bottom 0.254: 223.52,82.55 222.25,81.28 E5.11 | 223.52,82.55 228.6,82.55 229.87,83.82 E2.3 234.95,83.82 237.49,81.28 E2.11 | 210.82,85.09 33.02,85.09 31.75,83.82 E39.3 | 210.82,85.09 212.09,83.82 E5.3 | 223.52,82.55 223.52,85.09 210.82,85.09
N$9
  Top 0.254: E31.5 80.64,79.38 80.64,80.65 E31.4 | R21.2 C2.2
  Bottom 0.254: R21.2 D2.C | E31.5 80.01,78.74 77.47,76.2 C2.2
N$10
  Top 0.254: E35.7 72.39,45.72 78.74,39.37 87,39.37 87,46.36 E30.12 95.25,54.61 95.25,77.47 E31.12
N$11
  Top 0.254: E23.12 130.81,77.47 130.81,59.69 E22.2
  Bottom 0.254: E28.4 100.33,45.72 101.6,46.99 107.95,46.99 109.22,45.72 E22.2
N$12  (via drill 0.61)
  Top 0.254: v72.39,74.93 v72.39,151.13
  Bottom 0.254: v72.39,74.93 77.47,74.93 80.01,77.47 101.6,77.47 109.22,69.85 205.74,69.85 212.09,76.2 E5.6 | v72.39,151.13 78.11,156.85 81.92,156.85 E32.6
N$13
  Top 0.254: E31.10 88.27,78.11 88.27,76.84 E31.9 D1.C R19.2 C1.2
N$14  (via drill 0.61)
  Top 0.254: v108.58,69.22 110.49,71.12 110.49,142.24 106.68,146.05 E25.1
  Bottom 0.254: v108.58,69.22 233.04,69.22 237.49,73.66 E2.8
N$15  (via drill 0.61)
  Top 0.254: v114.3,76.2 114.3,83.19 112.39,85.09 112.39,87 113.03,87.63 113.03,152.4 111.76,153.67 E25.6
  Bottom 0.254: v114.3,76.2 115.57,77.47 161.29,77.47 168.28,70.49 205.1,70.49 212.09,77.47 228.6,77.47 229.87,76.2 E2.6
N$16  (via drill 0.61)
  Top 0.254: v34.29,52.07 34.29,58.42 33.02,59.69 33.02,73.66 E39.6
  Bottom 0.254: v34.29,52.07 36.83,49.53 129.54,49.53 130.81,48.26 E18.3 133.35,48.26 135.25,46.36 139.06,46.36 E18.11 140.97,45.72 142.24,44.45 143.51,44.45 | 143.51,44.45 152.4,44.45 153.67,45.72 E17.11 | 143.51,44.45 E17.3
N$17  (via drill 0.61)
  Top 0.254: v76.2,67.95 74.93,69.22 74.93,142.24 78.74,146.05 E32.1 | v220.98,67.95 E5.8
  Bottom 0.254: v220.98,67.95 v76.2,67.95
N$18  (via drill 0.61)
  Top 0.254: E31.8 87,75.57 87,84.46 E31.13 95.25,92.71 95.25,93.35 v97.16,95.25 | v121.28,95.25 121.28,107.32 123.19,109.22 E24.11
  Bottom 0.254: v97.16,95.25 v121.28,95.25
N$19
  Top 0.254: C1.1 R20.1
  Bottom 0.254: E31.11 C1.1
N$20
  Top 0.254: C2.1 R22.1
  Bottom 0.254: R22.1 E31.3
N$21  (via drill 0.61)
  Top 0.254: E42.10 24.77,45.09 24.77,76.84 E43.10 | E18.10 145.41,43.18 145.41,43.82 E17.4 | v168.28,71.76 163.19,66.68 163.19,52.71 E14.5
  Bottom 0.254: E42.4 19.05,45.72 21.59,43.18 E42.10 24.13,43.18 25.4,44.45 67.31,44.45 69.85,41.91 127,41.91 130.81,45.72 E18.4 135.89,45.72 138.43,43.18 E18.10 | E43.10 21.59,78.74 19.05,81.28 E43.4 | 236.22,80.01 234.95,81.28 E2.4 | 236.22,80.01 237.49,78.74 E2.10 | 236.22,80.01 223.52,80.01 222.25,78.74 E5.10 219.71,78.74 217.17,81.28 E5.4 212.09,81.28 202.56,71.76 v168.28,71.76 | 158.75,46.99 162.56,50.8 E14.5 | 158.75,46.99 E17.10 | 158.75,46.99 149.86,46.99 148.59,45.72 E17.4
N$22  (via drill 0.61)
  Top 0.254: E32.2 E32.7 | E25.2 E25.7 E26.2 E26.7 E27.2 E27.7 | E19.2 E19.7 E20.2 E20.7 | v162.56,135.89 162.56,48.26 E14.7
  Bottom 0.254: E32.2 84.45,144.15 106.05,144.15 E25.2 111.12,145.42 139.06,145.42 | v162.56,135.89 153.03,145.42 139.06,145.42 | 139.06,145.42 E19.2
N$23  (via drill 0.61)
  Top 0.254: 79.38,84.46 79.38,78.11 E31.6 | 79.38,84.46 E31.2 | v95.89,106.05 79.38,89.54 79.38,84.46
  Bottom 0.254: v95.89,106.05 97.79,107.95 100.33,107.95 102.87,110.49 119.38,110.49 123.19,114.3 E24.13
N$24  (via drill 0.61)
  Top 0.254: v123.19,137.16 123.19,165.1 116.84,165.1 E26.6 | v139.7,129.54 145.41,123.83 145.41,47.63 146.05,46.99 149.22,46.99 149.22,42.55 E17.6
  Bottom 0.254: v123.19,137.16 130.81,129.54 v139.7,129.54
N$25  (via drill 0.61)
  Top 0.254: v133.35,59.06 133.35,88.27 131.44,90.17 131.44,189.87 116.2,189.87 E27.6 | v130.81,56.52 130.18,55.88 130.18,42.55 E18.6
  Bottom 0.254: v133.35,59.06 v130.81,56.52
N$26  (via drill 0.61)
  Top 0.254: v95.89,34.29 95.89,53.98 98.42,56.52 98.42,96.52 96.52,96.52 95.25,97.79 95.25,100.33 97.16,102.24 97.16,107.32 93.98,107.32 92.71,108.59 92.71,120.65 103.5,131.45 103.5,173.36 106.68,176.53 E27.1 | v140.97,31.75 140.34,32.39 140.34,37.47 E18.8
  Bottom 0.254: v95.89,34.29 98.42,31.75 v140.97,31.75
N$27  (via drill 0.61)
  Top 0.254: v97.16,34.29 97.16,53.98 101.6,58.42 101.6,120.65 104.14,123.19 104.14,158.75 106.68,161.29 E26.1 | v153.03,33.02 154.94,34.93 E17.8
  Bottom 0.254: v97.16,34.29 98.42,33.02 v153.03,33.02
N$28
  Top 0.254: C3.1 R26.1
  Bottom 0.254: E23.11 C3.1
N$29  (via drill 0.61)
  Top 0.254: v43.18,33.02 77.47,67.31 77.47,111.13 102.23,135.89 v102.23,172.72
  Bottom 0.254: v43.18,33.02 13.34,33.02 13.34,38.74 E42.6 | v102.23,172.72 102.87,172.09 123.19,172.09 123.83,171.45 133.35,171.45 133.99,172.09 137.79,172.09 E20.6
N$30  (via drill 0.61)
  Top 0.254: v43.18,39.37 48.9,45.09 48.9,186.06 53.34,190.5 132.08,190.5 132.08,166.37 134.62,163.83 E20.1
  Bottom 0.254: v43.18,39.37 25.4,39.37 24.13,38.1 E42.8
N$31
  Top 0.254: 79.38,49.53 69.85,49.53 E35.3 | 79.38,49.53 79.38,42.55 E30.6 | 79.38,49.53 79.38,53.98 83.82,58.42 83.82,86.36 E31.1
N$32  (via drill 0.61)
  Top 0.254: E23.8 122.56,75.57 122.56,84.46 E23.13 | v113.67,87 113.67,126.37 E24.2
  Bottom 0.254: v113.67,87 114.3,87.63 118.11,87.63 119.38,86.36 E23.13
N$33
  Top 0.254: E23.5 116.2,79.38 116.2,80.65 E23.4 | D4.C R27.2 C4.2
  Bottom 0.254: E23.5 115.57,78.74 113.03,76.2 C4.2
N$34
  Top 0.254: C4.1 R28.1
  Bottom 0.254: R28.1 E23.3
N$35  (via drill 0.61)
  Top 0.254: v69.85,53.34 64.77,48.26 E35.1 | v90.17,92.71 84.45,87 84.45,56.52 E30.1
  Bottom 0.254: E30.1 v69.85,53.34 | v90.17,92.71 90.81,92.08 248.28,92.08 248.28,93.98 236.22,106.05 236.22,109.22 237.49,110.49 240.66,110.49 240.66,117.48 E3.12
N$37
  Top 0.254: E23.6 114.94,78.11 114.94,84.46 E23.2 114.3,88.9 114.3,121.92 E24.4
N$38  (via drill 0.61)
  Top 0.254: v127.64,87.63 131.44,83.82 131.44,58.42 128.27,55.25 128.27,45.72 125.73,43.18 E22.6
  Bottom 0.254: E28.10 107.95,43.18 109.22,44.45 120.65,44.45 121.92,43.18 E22.6 | v127.64,87.63 119.38,87.63 118.11,88.9 E23.1
N$39
  Top 0.254: C5.1 R30.1
  Bottom 0.254: R30.1 E29.3
N$40
  Top 0.254: E29.6 97.16,113.67 97.16,120.02 E29.2
  Bottom 0.254: E24.6 115.57,119.38 114.3,120.65 101.6,120.65 100.33,121.92 E29.2
N$41
  Top 0.254: E42.3 13.34,50.17 13.34,81.92 E43.3
  Bottom 0.254: E42.11 21.59,45.72 19.05,48.26 E42.3 | E43.11 21.59,81.28 20.95,81.92 18.41,81.92 16.51,83.82 E43.3 13.34,83.82 13.34,75.57 13.97,74.93 35.56,74.93 36.83,73.66 E39.8
N$46
  Bottom 0.254: E16.12 173.99,149.86 175.26,148.59 199.39,148.59 203.2,144.78 E10.10
N$48
  Bottom 0.254: E28.12 107.95,48.26 109.22,46.99 121.92,46.99 123.19,45.72 E22.7
N$49
  Top 0.254: E28.6 103.5,36.2 103.5,35.56 104.78,34.29 114.94,34.29 114.94,41.28 E22.3
N$50
  Bottom 0.254: E28.8 107.95,38.1 109.22,39.37 121.92,39.37 123.19,40.64 E22.5
N$51
  Bottom 0.254: E35.2 64.77,45.72 66.04,46.99 78.74,46.99 80.01,45.72 E30.4
N$52
  Bottom 0.254: E35.6 72.39,43.18 73.66,44.45 86.36,44.45 87.63,43.18 E30.10
N$53
  Bottom 0.254: E35.5 72.39,40.64 73.66,39.37 86.36,39.37 87.63,38.1 E30.8
N$54
  Top 0.254: E15.11 PAD12.1
N$55
  Top 0.254: E15.10 PAD13.1
N$56
  Top 0.254: E15.13 PAD14.1
N$57
  Top 0.254: E15.12 PAD15.1
N$67  (via drill 0.61)
  Top 0.254: v134.62,82.55 138.43,86.36 138.43,152.4 139.7,153.67 E19.6
  Bottom 0.254: v134.62,82.55 29.21,82.55 24.13,77.47 17.78,77.47 16.51,76.2 E43.6
N$68  (via drill 0.61)
  Top 0.254: v132.72,138.43 134.62,140.34 E19.1
  Bottom 0.254: v132.72,138.43 12.7,138.43 12.7,73.66 13.97,72.39 20.32,72.39 21.59,73.66 E43.8
N$71
  Top 0.254: E16.9 PAD27.1
N$72
  Top 0.254: E16.10 PAD28.1
N$73  (via drill 0.61)
  Top 0.254: v226.69,176.53 232.41,170.82 232.41,144.15 231.14,142.88 JP4.1
  Bottom 0.254: v226.69,176.53 211.46,176.53 211.46,174.63 E8.6
N$74
  Top 0.254: E16.11 PAD29.1
N$75
  Top 0.254: E16.8 PAD30.1
N$76
  Top 0.254: E29.9 PAD31.1
N$77
  Top 0.254: E29.10 PAD32.1
N$78
  Top 0.254: E29.8 PAD33.1
N$79
  Top 0.254: E29.12 PAD34.1
N$80
  Top 0.254: E29.13 PAD35.1
N$81
  Top 0.254: E29.11 PAD36.1
N$87
  Top 0.254: E39.12 PAD42.1
N$88
  Top 0.254: E39.13 PAD43.1
N$89
  Top 0.254: E39.11 PAD44.1
N$92
  Bottom 0.254: E16.6 166.37,142.24 167.64,140.97 182.88,140.97 186.69,144.78 E13.10
N$94
  Bottom 0.254: E21.1 137.16,180.34 152.4,180.34 167.64,165.1 227.97,165.1 243.21,149.86 243.21,109.86 239.4,109.86 E3.8
N$96  (via drill 0.61)
  Top 0.254: v205.74,55.88 200.66,60.96 200.66,109.22 E9.6
  Bottom 0.254: v205.74,55.88 209.55,55.88 212.09,53.34 E4.4
N$100  (via drill 0.61)
  Top 0.254: v216.53,53.34 215.9,53.98 215.9,81.28 214.63,82.55 211.46,82.55 211.46,122.56 212.09,123.19 215.26,123.19 215.26,134.62 208.28,141.61 v208.28,142.24
  Bottom 0.254: v208.28,142.24 207.01,143.51 200.66,143.51 199.39,142.24 E10.6 | v216.53,53.34 E4.17
N$101  (via drill 0.61)
  Top 0.254: v241.94,46.99 v241.94,128.27
  Bottom 0.254: v241.94,46.99 223.52,46.99 222.25,48.26 E4.15 | v241.94,128.27 234.31,135.89 210.82,135.89 207.01,139.7 E10.8
N$103  (via drill 0.61)
  Top 0.254: v215.26,143.51 215.26,150.5 E7.2
  Bottom 0.254: v215.26,143.51 231.78,143.51 233.04,142.24 JP4.3
N$104  (via drill 0.61)
  Top 0.254: v162.56,41.91 160.02,44.45 160.02,116.84 157.48,119.38 v157.48,146.69
  Bottom 0.254: v162.56,41.91 218.44,41.91 219.71,43.18 E4.13 | v157.48,146.69 158.12,146.05 181.61,146.05 182.25,145.42 182.25,142.88 180.97,142.88 E13.6
N$108  (via drill 0.61)
  Top 0.254: v224.16,148.59 223.52,149.23 223.52,172.72 222.25,173.99 219.07,173.99 219.07,172.09 E8.8
  Bottom 0.254: v224.16,148.59 215.9,148.59 214.63,149.86 E7.3
N$109  (via drill 0.61)
  Top 0.254: v197.49,39.37 195.58,41.28 v195.58,57.79 | v196.22,59.69 185.42,70.49 185.42,116.84 186.69,118.11 189.87,118.11 189.87,120.02 189.23,120.65 185.42,120.65 185.42,138.43 186.69,139.7 E13.8
  Bottom 0.254: v197.49,39.37 218.44,39.37 219.71,38.1 E4.11 | v195.58,57.79 195.58,59.69 v196.22,59.69
N$111
  Bottom 0.254: E7.4 214.63,147.32 215.9,146.05 234.31,146.05 234.95,145.42 234.95,142.88 236.22,142.88 JP4.5
N$113  (via drill 0.61)
  Top 0.254: v209.55,163.83 209.55,179.07 E11.13
  Bottom 0.254: v209.55,163.83 215.9,157.48 JP3.2 JP3.4
N$128
  Top 0.254: JP2.6 JP2.4
  Bottom 0.254: JP2.4 JP2.2 | E11.2 199.39,182.88 203.2,186.69 231.78,186.69 236.22,182.25 JP2.6
N$129
  Top 0.254: E11.1 203.84,185.42 203.84,186.06 205.1,187.33 231.14,187.33 JP1.2 JP1.4
N$132
  Bottom 0.254: E11.12 207.01,180.34 208.28,181.61 218.44,181.61 219.71,180.34 E8.12
VCC  (via drill 0.61)
  Top 0.635: E7.14 219.71,156.21 C13.1 | E10.14 204.47,156.21 C16.1 203.84,167.64 203.84,183.52 E11.14 | E19.8 134.62,156.21 135.89,157.48 135.89,167.64 134.62,168.91 E20.8 134.62,171.45 133.35,172.72 133.35,182.88 134.62,184.15 E21.8 | E16.14 170.81,153.04 170.81,137.16 C21.1 171.45,125.73 E15.14 170.81,122.56 170.81,107.95 171.45,107.32 C20.1 | E12.14 186.69,125.73 C18.1 | E9.14 204.47,125.73 C15.1 | E6.14 219.71,125.73 C12.1 | 237.49,105.41 237.49,90.17 E2.14 | 237.49,105.41 C8.1 | C11.1 219.71,99.7 225.43,93.98 R15.1 226.06,92.71 222.25,88.9 E5.14 219.07,87 219.07,71.12 C10.1 219.71,60.96 E4.20 219.07,59.06 219.07,36.83 219.71,36.2 C9.1 | E1.20 238.12,61.6 238.12,71.12 C7.1 | 237.49,105.41 240.66,108.59 240.66,122.56 E3.14 | E40.8 22.86,163.83 21.59,165.1 21.59,180.34 22.86,181.61 E41.8 | E36.8 50.8,171.45 52.07,172.72 52.07,182.88 50.8,184.15 E37.8 | E34.8 78.74,184.15 77.47,182.88 77.47,172.72 78.74,171.45 E33.8 78.74,168.91 80.01,167.64 80.01,157.48 78.74,156.21 E32.8 | R20.2 93.98,92.71 90.17,88.9 E31.14 85.72,85.73 85.72,73.66 87.63,71.76 C36.1 87.63,54.61 E30.14 | C29.1 123.19,106.05 129.54,99.7 R26.2 129.54,93.35 125.73,89.54 125.73,88.9 E23.14 121.28,85.73 121.28,73.66 123.19,71.76 C28.1 | 107.95,172.72 107.95,182.88 106.68,184.15 E27.8 | 107.95,172.72 106.68,171.45 E26.8 | 107.95,172.72 107.95,157.48 106.68,156.21 E25.8 106.68,153.67 105.41,152.4 105.41,124.46 E29.14 104.78,122.56 104.78,107.95 105.41,107.32 C34.1 | C37.1 88.9,153.04 93.98,147.96 R30.2 | E38.20 36.83,62.23 C44.1 | E43.14 20.95,87 20.95,71.12 C48.1 22.23,71.12 22.23,53.98 E42.14 20.95,51.44 20.95,36.83 21.59,36.2 C47.1
  Top 0.635: 69.85,32.39 83.82,32.39 87,35.56 C35.1 | 69.85,32.39 C40.1 69.22,38.1 69.22,46.36 E35.8 | 69.85,32.39 60.96,32.39 60.96,28.58 59.05,26.67 C52.+ | 104.78,44.45 104.78,51.44 E28.14 | 104.78,44.45 104.78,36.83 105.41,36.2 C33.1 | 122.56,44.45 122.56,38.1 C27.1 123.19,37.47 126.36,34.29 126.36,26.67 C51.+ v127,19.05 | 122.56,44.45 122.56,46.36 E22.8 | E18.14 137.79,51.44 137.79,35.56 C23.1 | E17.14 153.03,51.44 153.03,35.56 C22.1 | E14.20 170.81,59.06 170.81,35.56 C19.1 | 122.56,44.45 104.78,44.45
  Bottom 0.635: E8.14 219.71,185.42 218.44,184.15 208.28,184.15 207.01,185.42 E11.14 | C13.1 219.07,167.64 217.81,168.91 212.09,168.91 210.82,167.64 C16.1 | R17.1 146.69,185.42 145.41,184.15 C26.1 144.78,183.52 136.53,183.52 E21.8 | E19.8 136.53,156.85 144.78,156.85 C24.1 170.18,153.67 171.45,154.94 E16.14 173.99,154.94 175.26,156.21 185.42,156.21 186.69,154.94 E13.14 189.23,154.94 190.5,153.67 203.2,153.67 204.47,154.94 E10.14 | C25.1 144.15,168.91 143.51,168.28 136.53,168.28 E20.8 | C20.1 172.09,106.68 173.35,105.41 184.78,105.41 186.06,106.68 C17.1 197.49,106.68 198.75,107.95 206.38,107.95 | U$1.AA2 260.99,13.97 250.19,24.77 C49.+ 247.65,26.04 238.12,35.56 C6.1 236.85,35.56 235.59,34.29 228.6,34.29 227.33,35.56 C9.1 219.07,35.56 217.81,34.29 202.56,34.29 194.31,26.04 C50.+ 192.41,24.13 192.41,17.15 191.77,16.51 191.77,13.97 U$1.BA2 | E12.14 195.58,124.46 196.85,125.73 203.2,125.73 204.47,124.46 E9.14 207.01,124.46 208.28,125.73 223.52,125.73 | 223.52,125.73 236.22,125.73 237.49,124.46 E3.14 | 223.52,125.73 222.25,124.46 E6.14 | 206.38,107.95 205.1,106.68 C14.1 | 206.38,107.95 217.81,107.95 219.07,106.68 C11.1 | E2.14 237.49,88.9 236.22,90.17 223.52,90.17 222.25,88.9 E5.14 | 218.44,62.23 207.65,62.23 206.38,60.96 R11.1 E14.20 | 218.44,62.23 219.71,60.96 E4.20 | 218.44,62.23 236.22,62.23 237.49,60.96 E1.20 | C45.1 32.38,161.29 31.75,160.66 24.77,160.66 E40.8 | C46.1 32.38,181.61 31.75,180.98 24.77,180.98 E41.8 29.84,189.87 55.24,189.87 | C41.1 60.33,168.91 59.69,168.28 52.7,168.28 E36.8 | C42.1 60.96,183.52 52.7,183.52 E37.8 55.24,189.87 | E32.8 80.64,153.04 88.9,153.04 C37.1
  Bottom 0.635: C38.1 88.27,168.91 87.63,168.28 80.64,168.28 E33.8 | C39.1 88.9,187.33 80.64,187.33 E34.8 74.3,189.87 55.24,189.87 | R22.2 R20.2 R28.2 R26.2 | E25.8 108.58,153.04 116.84,153.04 C30.1 | C31.1 116.2,168.91 115.57,168.28 108.58,168.28 E26.8 | C32.1 116.84,187.33 108.58,187.33 E27.8 | R30.2 94.61,129.54 98.42,125.73 104.14,125.73 105.41,124.46 E29.14 115.57,133.35 121.92,133.35 123.19,132.08 E24.20 | C29.1 122.56,106.68 121.28,107.95 110.49,107.95 109.22,106.68 C34.1 | C47.1 22.23,35.56 23.5,34.29 34.92,34.29 36.2,35.56 C43.1 60.33,35.56 64.14,39.37 67.94,39.37 69.22,38.1 C40.1 | E39.14 36.83,88.9 35.56,90.17 25.4,90.17 24.13,88.9 E43.14 | C44.1 36.2,71.12 34.92,72.39 23.5,72.39 22.23,71.12 C48.1 | C52.+ 57.78,24.13 57.78,13.97 U$1.DA2 | 136.53,36.83 137.79,35.56 C23.1 | 136.53,36.83 125.09,36.83 123.83,38.1 C27.1 | 151.76,36.83 153.03,35.56 C22.1 | 151.76,36.83 136.53,36.83 | 151.76,36.83 169.54,36.83 170.81,35.56 C19.1 | E30.14 90.17,53.34 91.44,52.07 104.14,52.07 105.41,53.34 E28.14 | v127,19.05 127,13.97 U$1.CA2 | C35.1 98.42,35.56 99.69,36.83 103.5,36.83 104.78,35.56 C33.1

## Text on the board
Bottom: VRS
tPlace: Fold in ECOs. | WARNING: DO NOT USE WITH OMNIBUS CPU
